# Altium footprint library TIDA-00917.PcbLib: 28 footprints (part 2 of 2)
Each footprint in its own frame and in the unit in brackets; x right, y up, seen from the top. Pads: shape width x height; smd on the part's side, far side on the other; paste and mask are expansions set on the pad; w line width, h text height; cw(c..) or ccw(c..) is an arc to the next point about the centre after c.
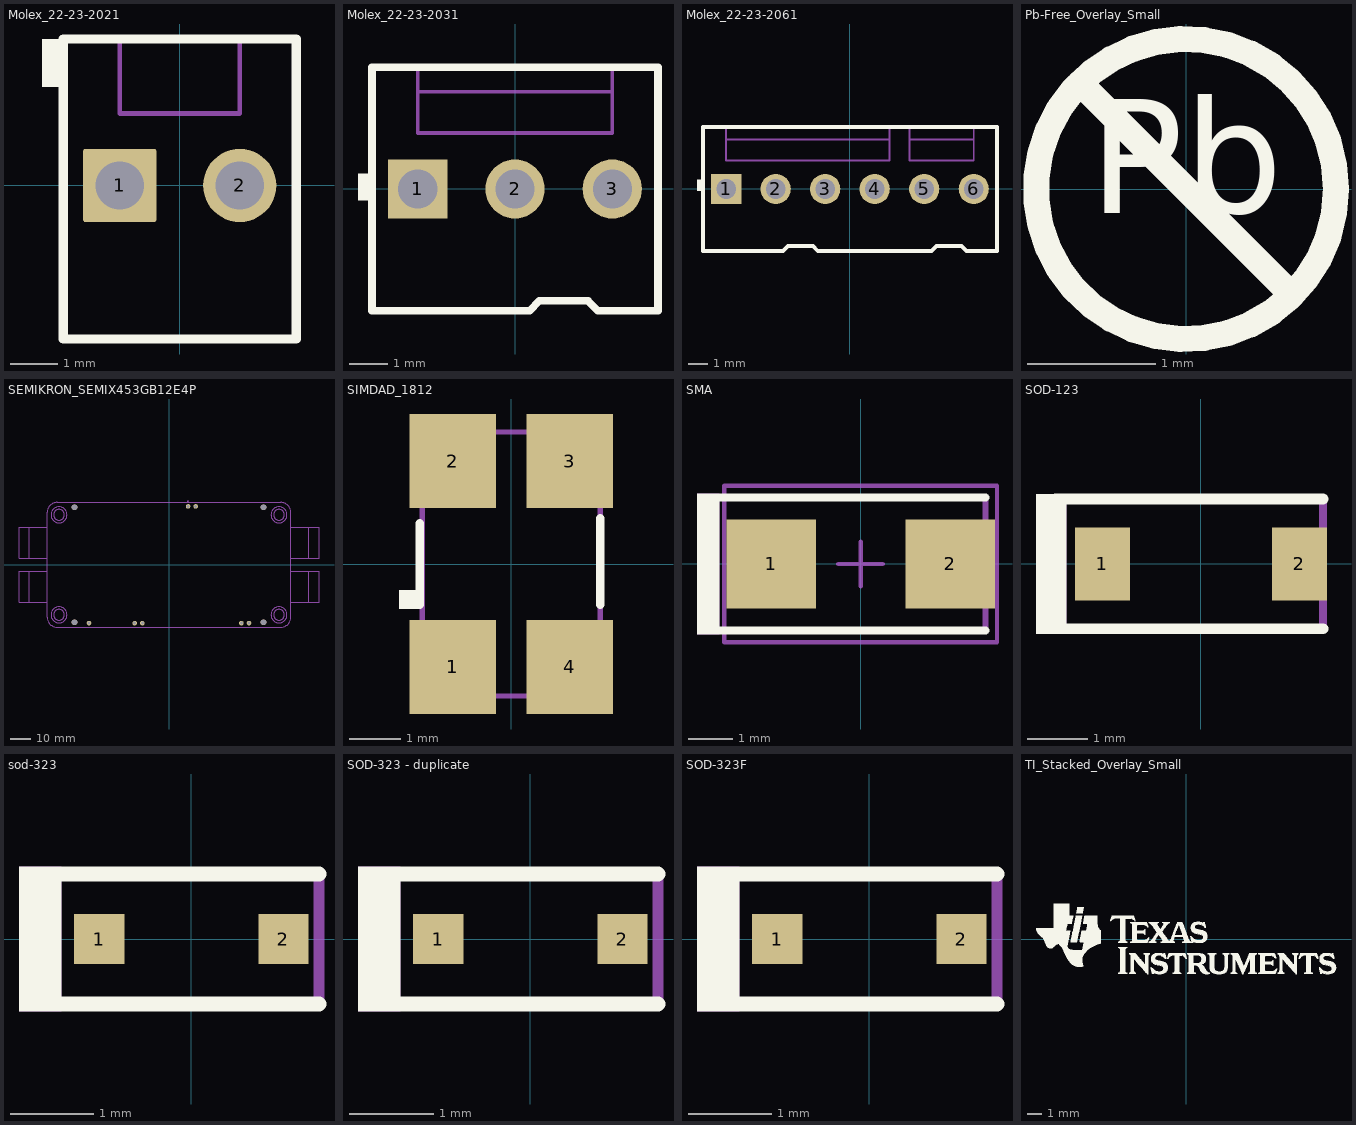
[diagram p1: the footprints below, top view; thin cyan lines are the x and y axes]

## Molex_22-23-2021 [mm] "Header, 2.54mm, 2x1, TH"
height 10.66
pads (2):
  rrect6% 1.55x1.55 hole 1.02: 1(-1.27,0)
  round 1.55 hole 1.02: 2(1.27,0)
Top Overlay:
  region: -2.449,3.1 -2.921,3.1 -2.921,2.084 -2.449,2.084
  lines w0.2: -2.465,-3.25 -2.465,3.1 2.465,3.1 2.465,-3.25 -2.465,-3.25
Mechanical 5:
  lines w0.1: -1.27,3.1 -1.27,1.524 1.27,1.524 1.27,3.1 ; -2.465,-3.25 2.465,-3.25 2.465,3.1 -2.465,3.1 -2.465,-3.25
  text ".Designator" at 0.382,-1.346 h0.76
3D body "022232021.stp": height 10.08, standoff -4.14, extent -2.465,-3.25 2.463,3.1

## Molex_22-23-2031 [mm] "Header, 2.54mm, 3x1, TH"
height 11.3
pads (3):
  rect 1.55x1.55 hole 1.02: 1(-2.54,0)
  round 1.55 hole 1.02: 2(0,0) 3(2.54,0)
Top Overlay:
  rectangle: -4.1,-0.3 -3.8,0.4
  lines w0.2: -3.734,-3.175 -3.734,3.175 -2.54,3.175 2.54,3.175 3.734,3.175 3.734,-3.175 2.159,-3.175 1.905,-2.921 0.635,-2.921 0.381,-3.175 -3.734,-3.175
Mechanical 5:
  lines w0.1: -2.54,2.54 -2.54,1.46 2.54,1.46 2.54,2.54 ; -2.54,2.54 2.54,2.54 ; -2.54,2.54 -2.54,3.175 ; -2.54,3.175 -3.734,3.175 -3.734,-3.175 0.381,-3.175 0.635,-2.921 1.905,-2.921 2.159,-3.175 3.734,-3.175 3.734,3.175 2.54,3.175 ; -2.54,3.175 2.54,3.175 ; 2.54,2.54 2.54,3.175
  text ".Designator" at 0.279,-0.738 h0.76
3D body "022232031.stp": height 10.67, standoff -3.56, extent -3.734,-3.251 3.734,3.099

## Molex_22-23-2061 [mm] "Header, 2.54mm, 6x1, TH"
height 11.3
pads (6):
  rect 1.55x1.55 hole 1.02: 1(-6.35,0)
  round 1.55 hole 1.02: 2(-3.81,0) 3(-1.27,0) 4(1.27,0) 5(3.81,0) 6(6.35,0)
Top Overlay:
  rectangle: -7.849,-0.102 -7.544,0.482
  lines w0.2: -7.544,-3.175 -3.429,-3.175 -3.175,-2.921 -1.905,-2.921 -1.651,-3.175 4.191,-3.175 4.445,-2.921 5.715,-2.921 5.969,-3.175 7.544,-3.175 7.544,3.175 6.35,3.175 3.048,3.175 2.032,3.175 -6.35,3.175 -7.544,3.175 -7.544,-3.175
Mechanical 5:
  lines w0.1: -6.35,2.54 -6.35,1.46 2.032,1.46 2.032,2.54 ; -6.35,2.54 -6.35,3.175 ; -6.35,2.54 2.032,2.54 ; -6.35,3.175 2.032,3.175 ; -6.35,3.175 -7.544,3.175 -7.544,-3.175 -3.429,-3.175 -3.175,-2.921 -1.905,-2.921 -1.651,-3.175 4.191,-3.175 4.445,-2.921 5.715,-2.921 5.969,-3.175 7.544,-3.175 7.544,3.175 6.35,3.175 ; 2.032,2.54 2.032,3.175 ; 2.032,3.175 3.048,3.175 ; 3.048,2.54 3.048,1.46 6.35,1.46 6.35,2.54 ; 3.048,2.54 3.048,3.175 ; 3.048,2.54 6.35,2.54 ; 3.048,3.175 6.35,3.175 ; 6.35,2.54 6.35,3.175
  text ".Designator" at 0.406,-0.687 h0.76
3D body "022232061.stp": height 10.67, standoff -3.56, extent -7.544,-3.251 7.544,3.099

## Pb-Free_Overlay_Small [mm]
Top Overlay:
  circle w0.203: c0,0 r1.168
  lines w0.203: -0.826,0.826 0.826,-0.826
  text "Pb" at -0.752,-0.48 h1.52

## SEMIKRON_SEMIX453GB12E4P [mm] "TH, 11-Leads, Body 150x62.4mm"
height 17.5
pads (19):
  round 2.3 hole 1.5: 1(9.53,29.2) 2(13.34,29.2) 5(40,-29.2) 6(36.19,-29.2) 7(-13.33,-29.2) 8(-17.15,-29.2) 9(-40,-29.2)
  round 0 all layers, no hole paste-6 mask+0: 3(68.5,11) 4(68.5,-11) 10(-68.5,-11) 11(-68.5,11)
  rect 0x0 smd mask+0: 3(68.5,11) 4(68.5,-11) 10(-68.5,-11) 11(-68.5,11)
  round 2.8 hole 2.8 unplated mask+0: MH1(-47.25,28.75) MH2(47.25,28.75) MH3(47.25,-28.75) MH4(-47.25,-28.75)
Mechanical 5:
  text ".Designator" at -2,-0.7 h0.64
Mechanical 13:
  circle w0.1: c55,-25 r2.7
  circle w0.1: c55,25 r2.7
  circle w0.1: c55,-25 r4
  circle w0.1: c55,25 r4
  circle w0.1: c-55,25 r2.7
  circle w0.1: c-55,-25 r4
  circle w0.1: c-55,25 r4
  circle w0.1: c-55,-25 r2.7
  circle w0.1: c-55,25 r4
  circle w0.1: c55,25 r4
  circle w0.1: c-55,-25 r4
  circle w0.1: c55,-25 r4
  lines w0.1: -60.9,-18.75 -70,-18.75 ; -60.9,-3.25 -70,-3.25 ; -60.9,3.25 -70,3.25 ; -60.9,18.75 -70,18.75 ; 60.9,-18.75 70,-18.75 ; 60.9,-3.25 70,-3.25 ; 60.9,3.25 70,3.25 ; 60.9,18.75 70,18.75 ; -70,-18.75 -75,-18.75 -75,-3.25 -70,-3.25 ; -70,-18.75 -70,-3.25 ; -70,3.25 -75,3.25 -75,18.75 -70,18.75 ; -70,3.25 -70,18.75 ; 70,-18.75 75,-18.75 75,-3.25 70,-3.25 ; 70,-18.75 70,-3.25 ; 70,3.25 70,18.75 ; 70,3.25 75,3.25 75,18.75 70,18.75 ; -60.9,-26.2 ccw(c-55.9,-26.2) -55.9,-31.2 55.9,-31.2 ccw(c55.9,-26.2) 60.9,-26.2 60.9,26.2 ccw(c55.9,26.2) 55.9,31.2 -55.9,31.2 ccw(c-55.9,26.2) -60.9,26.2 -60.9,-26.2
Mechanical 15:
  lines w0.2: -75,-17.7 -75,-18.75 -60.9,-18.75 -60.9,-26.2 ccw(c-55.9,-26.2) -55.9,-31.2 55.9,-31.2 ccw(c55.9,-26.2) 60.9,-26.2 60.9,-18.75 75,-18.75 75,-17.7 ; -75,-4.3 -75,-3.25 -60.9,-3.25 -60.9,3.25 -75,3.25 -75,4.3 ; -75,17.7 -75,18.75 -60.9,18.75 -60.9,26.2 cw(c-55.9,26.2) -55.9,31.2 55.9,31.2 cw(c55.9,26.2) 60.9,26.2 60.9,18.75 75,18.75 75,17.7 ; 75,-4.3 75,-3.25 60.9,-3.25 60.9,3.25 75,3.25 75,4.3 ; 9.25,32 9.75,32 9.5,31.5 9.25,32
3D body "SEMIX453GB12E4P.stp": height 17, standoff 0, extent -75,-31.2 75,31.2

## SIMDAD_1812 [mm] "EPCOS"
height 3
pads (4):
  rect 1.7x1.85 smd: 1(-1.15,-2.025) 2(-1.15,2.025) 3(1.15,2.025) 4(1.15,-2.025)
Top Overlay:
  rectangle: -2.203,-0.889 -1.778,-0.514
  lines w0.17: -1.8,-0.8 -1.8,0.8 ; 1.75,-0.8 1.75,0.9
Mechanical 5:
  circle w0.1: c-1.143,-1.905 r0.3
  lines w0.1: -1.75,-2.6 -1.75,2.6 1.75,2.6 1.75,-2.6 -1.75,-2.6
  text ".Designator" at -0.585,0.051 h0.76
3D body: height 3, standoff 0, extent -1.749,-2.599 1.749,2.599
3D body: height 3.01, standoff 2, extent -1.199,1.101 -0.601,1.699

## SMA [mm] "Molded Diode, 2-Leads, Body 4.3x2.6mm, IPC Medium Density, based on OnSemi component dimensions and land pattern"
height 2.27
pads (2):
  rect 2x2 smd: 1(-2,0) 2(2,0)
Top Overlay:
  rectangle: -3.658,-1.575 -3.15,1.575
  lines w0.178: -3.327,-1.486 2.794,-1.486 ; -3.327,1.486 2.794,1.486
Mechanical 5:
  rectangle: -3.658,-1.575 -3.15,1.575
  lines w0.127: -3.327,-1.486 2.794,-1.486 2.794,1.486 -3.327,1.486
  text ".Designator" at -0.407,-0.343 h0.76
Mechanical 15:
  lines w0.1: -0.5,0 0.5,0 ; 0,-0.5 0,0.5 ; -3.05,-1.75 -3.05,1.75 3.05,1.75 3.05,-1.75 -3.05,-1.75
3D body "SMA_nominal.stp": height 2.42, standoff 0.02, extent -2.6,-1.3 2.6,1.3

## SOD-123 [mm] "On Semi recommended land pattern"
height 1.35
pads (2):
  rect 0.915x1.22 smd: 1(-1.637,0) 2(1.637,0)
Top Overlay:
  rectangle: -2.743,-1.169 -2.235,1.168
  lines w0.178: -2.413,-1.079 2.032,-1.079 ; -2.413,1.079 2.032,1.079
Mechanical 5:
  rectangle: -2.743,-1.169 -2.235,1.168
  lines w0.127: -2.413,-1.079 2.032,-1.079 2.032,1.079 -2.413,1.079
  text ".Designator" at 0.356,0.278 h0.76
3D body "SOD-123.stp": height 1.35, standoff 0, extent -1.932,-0.9 1.932,0.9

## sod-323 [mm] "NXP recommended land pattern"
height 1.15
pads (2):
  rect 0.6x0.6 smd paste-0.05: 1(-1.1,0) 2(1.1,0)
Top Overlay:
  rectangle: -2.057,-0.864 -1.549,0.864
  lines w0.178: -1.803,-0.775 0.1,-0.775 1.525,-0.775 ; -1.803,0.775 0.1,0.775 1.525,0.775
Mechanical 5:
  rectangle: -2.057,-0.864 -1.549,0.864
  lines w0.127: -1.803,-0.775 0.1,-0.775 1.525,-0.775 1.525,0.775 0.1,0.775 -1.803,0.775
  text ".Designator" at -0.738,-0.279 h0.76
3D body "SOD-323.stp": height 1.1, standoff 0, extent -1.3,-0.675 1.3,0.675

## SOD-323 - duplicate [mm]
pads (2):
  rect 0.6x0.6 smd paste-0.05: 1(-1.1,0) 2(1.1,0)
Top Overlay:
  rectangle: -2.057,-0.863 -1.549,0.864
  lines w0.178: -1.803,-0.775 0.1,-0.775 1.525,-0.775 ; -1.803,0.775 0.1,0.775 1.525,0.775
Mechanical 5:
  rectangle: -2.057,-0.863 -1.549,0.864
  lines w0.127: -1.803,-0.775 0.1,-0.775 1.525,-0.775 1.525,0.775 0.1,0.775 -1.803,0.775
  text ".Designator" at -0.611,-0.265 h0.76
3D body "SOD-323.stp": height 1.1, standoff 0, extent -1.3,-0.675 1.3,0.675

## SOD-323F [mm] "NXP recommended land pattern"
height 0.8
pads (2):
  rect 0.6x0.6 smd paste-0.05: 1(-1.1,0) 2(1.1,0)
Top Overlay:
  rectangle: -2.057,-0.864 -1.549,0.864
  lines w0.178: -1.803,-0.775 0.1,-0.775 1.525,-0.775 ; -1.803,0.775 0.1,0.775 1.525,0.775
Mechanical 5:
  rectangle: -2.057,-0.864 -1.549,0.864
  lines w0.127: -1.803,-0.775 0.1,-0.775 1.525,-0.775 1.525,0.775 0.1,0.775 -1.803,0.775
  text ".Designator" at 0.636,0.381 h0.76
3D body "SOD-323F.stp": height 0.79, standoff -0.08, extent -1.35,-0.675 1.35,0.675

## TI_Stacked_Overlay_Small [mm]
Top Overlay:
  drawing of 18 lines, arcs and shapes, not listed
